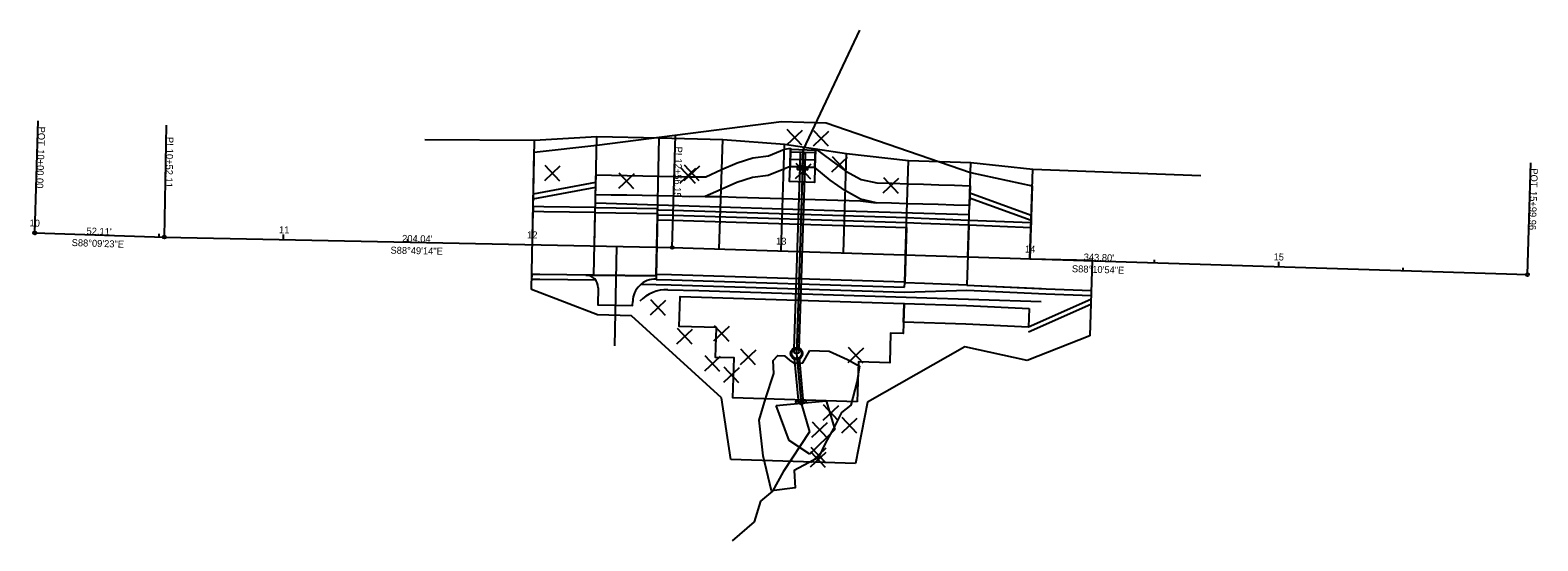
# Model space of a CAD drawing. Extents: x 2005219 to 2005824, y 572492 to 572698.
import ezdxf

# ---------------------------------------------------------------- set-up
doc = ezdxf.new("R2010")
doc.units = 0
for name, color, linetype in [('DR_P_Headwall', 7, 'Continuous'), ('GE_P_Alignment', 7, 'Continuous'), ('GE_P_Alignment_100_Bearings', 7, 'Continuous'), ('GE_P_Alignment_100_Cardinal_Points', 7, 'Continuous'), ('GE_P_Alignment_100_Distances', 7, 'Continuous'), ('GE_P_Alignment_100_Stations', 7, 'Continuous'), ('GE_X_Alignment_1000_Bearings', 7, 'Continuous'), ('GE_X_Alignment_1000_Cardinal_Points', 7, 'Continuous'), ('GE_X_Alignment_1000_Curve_Data', 7, 'Continuous'), ('GE_X_Alignment_1000_Distances', 7, 'Continuous'), ('GE_X_Alignment_1000_Stations', 7, 'Continuous'), ('GE_X_Alignment_100_Cardinal_Points', 7, 'Continuous'), ('GE_X_Alignment_100_Curve_Data', 7, 'Continuous'), ('GE_X_Alignment_100_Distances', 7, 'Continuous'), ('GE_X_Alignment_100_Stations', 7, 'Continuous'), ('GE_X_Alignment_500_Bearings', 7, 'Continuous'), ('GE_X_Alignment_500_Cardinal_Points', 7, 'Continuous'), ('GE_X_Alignment_500_Curve_Data', 7, 'Continuous'), ('GE_X_Alignment_500_Stations', 7, 'Continuous'), ('GK_Drainage_Nodes', 7, 'Continuous'), ('PV_P_Drive', 7, 'Continuous'), ('PV_P_EOP', 7, 'Continuous'), ('PV_P_Shoulder', 7, 'Continuous'), ('RD_P_GR_Rt', 7, 'Continuous'), ('RW_X_CL', 7, 'Continuous'), ('RW_X_Esmt_ES', 7, 'Continuous')]:
    doc.layers.add(name, color=color, linetype=linetype)

msp = doc.modelspace()

# ---------------------------------------------------------------- linework, layer by layer
at = {"layer": 'DR_P_Headwall'}
for points in [[(2005527.91, 572642.55), (2005527.87, 572641.55), (2005526.88, 572641.58), (2005526.91, 572642.58), (2005530.9, 572642.45), (2005530.87, 572641.45), (2005529.87, 572641.48), (2005529.91, 572642.48)], [(2005529.36, 572547.73), (2005529.27, 572548.72), (2005530.26, 572548.82), (2005530.35, 572547.82), (2005526.37, 572547.45), (2005526.28, 572548.45), (2005527.27, 572548.54), (2005527.37, 572547.55)]]:
    msp.add_lwpolyline(points, dxfattribs=at)
at = {"layer": 'GE_P_Alignment'}
for p, q in [((2005220.42, 572616.04), (2005272.51, 572614.37)), ((2005272.51, 572614.37), (2005476.5, 572610.17)), ((2005476.5, 572610.17), (2005820.14, 572599.26))]:
    msp.add_line(p, q, dxfattribs=at)
at = {"layer": 'GE_P_Alignment_100_Cardinal_Points'}
for p, q in [((2005220.42, 572616.04), (2005221.87, 572661.02)), ((2005272.51, 572614.37), (2005273.44, 572659.36)), ((2005476.5, 572610.17), (2005477.93, 572655.14)), ((2005820.14, 572599.26), (2005821.56, 572644.24))]:
    msp.add_line(p, q, dxfattribs=at)
for centre in [(2005220.42, 572616.04), (2005272.51, 572614.37), (2005476.5, 572610.17), (2005820.14, 572599.26)]:
    msp.add_circle(centre, 0.6, dxfattribs=at)
at = {"layer": 'GE_P_Alignment_100_Stations'}
for p, q in [((2005220.42, 572616.04), (2005220.49, 572618.04)), ((2005270.4, 572614.44), (2005270.44, 572615.63)), ((2005320.39, 572613.38), (2005320.43, 572615.38)), ((2005370.38, 572612.35), (2005370.4, 572613.55)), ((2005420.37, 572611.32), (2005420.41, 572613.32)), ((2005470.35, 572610.29), (2005470.38, 572611.49)), ((2005520.33, 572608.78), (2005520.39, 572610.77)), ((2005570.31, 572607.19), (2005570.34, 572608.39)), ((2005620.28, 572605.6), (2005620.34, 572607.6)), ((2005670.26, 572604.02), (2005670.29, 572605.22)), ((2005720.23, 572602.43), (2005720.29, 572604.43)), ((2005770.21, 572600.84), (2005770.24, 572602.04))]:
    msp.add_line(p, q, dxfattribs=at)
at = {"layer": 'GE_X_Alignment_1000_Bearings'}
for p, q in [((2005524.14, 572650.06), (2005523.91, 572642.67)), ((2005524.14, 572650.06), (2005523.91, 572642.67)), ((2005533.9, 572642.36), (2005534.17, 572649.85)), ((2005533.9, 572642.36), (2005534.17, 572649.85)), ((2005445.78, 572631.4), (2005445.95, 572639.4)), ((2005445.78, 572631.4), (2005445.95, 572639.4)), ((2005596.2, 572634.99), (2005595.94, 572627)), ((2005596.2, 572634.99), (2005595.94, 572627)), ((2005493.96, 572565.99), (2005494.34, 572577.99)), ((2005518.26, 572546.7), (2005538.47, 572548.57)), ((2005523.49, 572532.62), (2005518.26, 572546.7)), ((2005538.47, 572548.57), (2005541.87, 572536.98)), ((2005541.87, 572536.98), (2005531.82, 572527.09)), ((2005531.82, 572527.09), (2005523.49, 572532.62))]:
    msp.add_line(p, q, dxfattribs=at)
for points in [[(2005490, 572638.62), (2005496.35, 572641.55), (2005502.69, 572644.27), (2005509, 572646.28), (2005515.28, 572647.06), (2005521.62, 572649.64), (2005524.14, 572650.06)], [(2005490, 572638.62), (2005496.35, 572641.55), (2005502.69, 572644.27), (2005509, 572646.28), (2005515.28, 572647.06), (2005521.62, 572649.64), (2005524.14, 572650.06)], [(2005534.17, 572649.85), (2005540.25, 572645.28), (2005546.36, 572640.89), (2005552.51, 572637.55), (2005558.72, 572636.17)], [(2005534.17, 572649.85), (2005540.25, 572645.28), (2005546.36, 572640.89), (2005552.51, 572637.55), (2005558.72, 572636.17)], [(2005523.91, 572642.67), (2005521.36, 572641.64), (2005515.12, 572639.06), (2005508.84, 572638.28), (2005502.52, 572636.27), (2005496.18, 572633.55), (2005489.84, 572630.62)], [(2005523.91, 572642.67), (2005521.36, 572641.64), (2005515.12, 572639.06), (2005508.84, 572638.28), (2005502.52, 572636.27), (2005496.18, 572633.55), (2005489.84, 572630.62)], [(2005558.47, 572628.18), (2005552.26, 572629.55), (2005546.11, 572632.9), (2005540, 572637.29), (2005533.9, 572642.36)], [(2005558.47, 572628.18), (2005552.26, 572629.55), (2005546.11, 572632.9), (2005540, 572637.29), (2005533.9, 572642.36)], [(2005445.95, 572639.4), (2005452.2, 572639.27), (2005458.45, 572639.14), (2005464.69, 572639.02), (2005470.93, 572638.89), (2005477.5, 572638.75), (2005483.75, 572638.55), (2005490, 572638.62)], [(2005445.95, 572639.4), (2005452.2, 572639.27), (2005458.45, 572639.14), (2005464.69, 572639.02), (2005470.93, 572638.89), (2005477.5, 572638.75), (2005483.75, 572638.55), (2005490, 572638.62)], [(2005558.72, 572636.17), (2005564.97, 572635.97), (2005571.21, 572635.77), (2005577.46, 572635.59), (2005583.71, 572635.39), (2005589.95, 572635.19), (2005596.2, 572634.99)], [(2005558.72, 572636.17), (2005564.97, 572635.97), (2005571.21, 572635.77), (2005577.46, 572635.59), (2005583.71, 572635.39), (2005589.95, 572635.19), (2005596.2, 572634.99)], [(2005489.84, 572630.62), (2005483.58, 572630.55), (2005477.33, 572630.75), (2005470.77, 572630.89), (2005464.53, 572631.02), (2005458.28, 572631.15), (2005452.03, 572631.27), (2005445.78, 572631.4)], [(2005489.84, 572630.62), (2005483.58, 572630.55), (2005477.33, 572630.75), (2005470.77, 572630.89), (2005464.53, 572631.02), (2005458.28, 572631.15), (2005452.03, 572631.27), (2005445.78, 572631.4)], [(2005595.94, 572627), (2005589.7, 572627.19), (2005583.45, 572627.39), (2005577.21, 572627.59), (2005570.96, 572627.78), (2005564.71, 572627.98), (2005558.47, 572628.18)], [(2005595.94, 572627), (2005589.7, 572627.19), (2005583.45, 572627.39), (2005577.21, 572627.59), (2005570.96, 572627.78), (2005564.71, 572627.98), (2005558.47, 572628.18)]]:
    msp.add_lwpolyline(points, dxfattribs=at)
for points in [[(2005533.71, 572636.36), (2005523.72, 572636.68), (2005523.91, 572642.67), (2005526.91, 572642.58), (2005526.88, 572641.58), (2005530.87, 572641.45), (2005530.9, 572642.45), (2005533.9, 572642.36)], [(2005550.92, 572548.17), (2005500.95, 572549.76), (2005501.46, 572565.75), (2005493.96, 572565.99), (2005494.34, 572577.99), (2005479.35, 572578.46), (2005479.73, 572590.46), (2005569.68, 572587.6), (2005569.3, 572575.61), (2005564.31, 572575.76), (2005563.92, 572563.77), (2005551.43, 572564.17)], [(2005550.92, 572548.17), (2005500.95, 572549.76), (2005501.46, 572565.75), (2005493.96, 572565.99), (2005494.34, 572577.99), (2005479.35, 572578.46), (2005479.73, 572590.46), (2005569.68, 572587.6), (2005569.3, 572575.61), (2005564.31, 572575.76), (2005563.92, 572563.77), (2005551.43, 572564.17)]]:
    msp.add_lwpolyline(points, close=True, dxfattribs=at)
at = {"layer": 'GE_X_Alignment_1000_Cardinal_Points'}
for centre, radius in [((2005526.53, 572567.55), 2.42), ((2005526.53, 572567.55), 2), ((2005526.55, 572568.41), 0.99)]:
    msp.add_circle(centre, radius, dxfattribs=at)
at = {"layer": 'GE_X_Alignment_1000_Curve_Data'}
for p, q in [((2005420.37, 572611.32), (2005421.23, 572653.31)), ((2005445.36, 572610.81), (2005446.27, 572654.8)), ((2005470.35, 572610.29), (2005471.26, 572654.28)), ((2005495.44, 572609.57), (2005496.84, 572653.54)), ((2005520.33, 572608.78), (2005521.7, 572651.75)), ((2005523.89, 572642.17), (2005524.11, 572649.17)), ((2005545.32, 572607.98), (2005546.59, 572647.96)), ((2005570.31, 572607.19), (2005571.51, 572645.17)), ((2005595.29, 572606.4), (2005596.5, 572644.38)), ((2005620.28, 572605.7), (2005621.43, 572641.68))]:
    msp.add_line(p, q, dxfattribs=at)
msp.add_circle((2005526.53, 572567.55), 2, dxfattribs=at)
at = {"layer": 'GE_X_Alignment_1000_Distances'}
msp.add_line((2005454.14, 572610.63), (2005453.32, 572570.64), dxfattribs=at)
at = {"layer": 'GE_X_Alignment_1000_Stations'}
for p, q in [((2005522.56, 572651.45), (2005528.84, 572657.35)), ((2005528.65, 572651.26), (2005522.75, 572657.54)), ((2005533.25, 572651.04), (2005539.53, 572656.94)), ((2005539.34, 572650.85), (2005533.44, 572657.13)), ((2005540.7, 572640.57), (2005546.98, 572646.46)), ((2005546.79, 572640.37), (2005540.89, 572646.66)), ((2005425.32, 572637.05), (2005431.6, 572642.94)), ((2005431.41, 572636.85), (2005425.51, 572643.14)), ((2005455.08, 572634), (2005461.36, 572639.9)), ((2005461.17, 572633.81), (2005455.27, 572640.09)), ((2005479.78, 572636.13), (2005486.06, 572642.03)), ((2005485.87, 572635.94), (2005479.97, 572642.22)), ((2005481.33, 572637.14), (2005487.61, 572643.04)), ((2005487.42, 572636.95), (2005481.52, 572643.23)), ((2005526.12, 572637.87), (2005532.4, 572643.77)), ((2005532.21, 572637.68), (2005526.32, 572643.96)), ((2005561.33, 572632.11), (2005567.62, 572638.01)), ((2005567.42, 572631.92), (2005561.53, 572638.2)), ((2005467.77, 572583.04), (2005474.05, 572588.93)), ((2005473.86, 572582.84), (2005467.96, 572589.13)), ((2005478.46, 572571.46), (2005484.74, 572577.36)), ((2005484.54, 572571.27), (2005478.65, 572577.55)), ((2005493.34, 572572.59), (2005499.63, 572578.49)), ((2005499.43, 572572.4), (2005493.54, 572578.68)), ((2005503.93, 572563.15), (2005510.22, 572569.04)), ((2005510.02, 572562.95), (2005504.13, 572569.24)), ((2005547.23, 572563.91), (2005553.52, 572569.81)), ((2005553.32, 572563.72), (2005547.43, 572570)), ((2005489.61, 572560.56), (2005495.9, 572566.46)), ((2005495.7, 572560.37), (2005489.81, 572566.65)), ((2005497.25, 572556.03), (2005503.54, 572561.92)), ((2005503.34, 572555.83), (2005497.45, 572562.12)), ((2005537.17, 572540.82), (2005543.46, 572546.71)), ((2005543.26, 572540.62), (2005537.37, 572546.91)), ((2005532.67, 572533.86), (2005538.95, 572539.76)), ((2005538.76, 572533.67), (2005532.86, 572539.95)), ((2005544.64, 572535.68), (2005550.92, 572541.57)), ((2005550.73, 572535.48), (2005544.83, 572541.77)), ((2005532.09, 572521.98), (2005538.37, 572527.88)), ((2005532.18, 572523.74), (2005538.47, 572529.64)), ((2005538.18, 572521.79), (2005532.28, 572528.07)), ((2005538.27, 572523.55), (2005532.38, 572529.83))]:
    msp.add_line(p, q, dxfattribs=at)
at = {"layer": 'GE_X_Alignment_100_Cardinal_Points'}
for p, q in [((2005446.24, 572651.27), (2005520.48, 572660.79)), ((2005520.48, 572660.79), (2005538.47, 572660.22)), ((2005538.47, 572660.22), (2005596.37, 572640.34)), ((2005420, 572593.35), (2005421.13, 572648.48)), ((2005421.13, 572648.48), (2005446.24, 572651.27)), ((2005596.37, 572640.34), (2005621.21, 572634.96)), ((2005621.21, 572634.96), (2005620.28, 572605.6)), ((2005620.28, 572605.6), (2005645.28, 572605.03)), ((2005645.28, 572605.03), (2005644.31, 572574.61)), ((2005446.53, 572583.14), (2005420, 572593.35)), ((2005460.56, 572589.71), (2005460.56, 572589.71)), ((2005460.17, 572582.71), (2005446.53, 572583.14)), ((2005496.33, 572549.72), (2005460.17, 572582.71)), ((2005644.31, 572574.61), (2005619.16, 572564.73)), ((2005594.14, 572570.19), (2005555, 572547.97)), ((2005619.16, 572564.73), (2005594.14, 572570.19)), ((2005500.16, 572524.96), (2005496.33, 572549.72)), ((2005555, 572547.97), (2005550.14, 572523.37)), ((2005550.14, 572523.37), (2005500.16, 572524.96))]:
    msp.add_line(p, q, dxfattribs=at)
at = {"layer": 'GE_X_Alignment_100_Curve_Data'}
for p, q in [((2005445.91, 572628.15), (2005495.88, 572626.56)), ((2005495.88, 572626.56), (2005545.86, 572624.97)), ((2005545.86, 572624.97), (2005595.83, 572623.39))]:
    msp.add_line(p, q, dxfattribs=at)
at = {"layer": 'GE_X_Alignment_100_Distances'}
for points in [[(2005489.84, 572630.62), (2005496.01, 572630.66), (2005502.26, 572630.46), (2005552.23, 572628.87), (2005558.47, 572628.18), (2005552.26, 572629.55), (2005546.11, 572632.9), (2005540, 572637.29), (2005533.9, 572642.36), (2005533.71, 572636.36), (2005523.72, 572636.68), (2005523.91, 572642.67), (2005521.36, 572641.64), (2005515.12, 572639.06), (2005515.12, 572639.06), (2005508.84, 572638.28), (2005502.52, 572636.27), (2005496.18, 572633.55)], [(2005489.84, 572630.62), (2005496.01, 572630.66), (2005502.26, 572630.46), (2005552.23, 572628.87), (2005558.47, 572628.18), (2005552.26, 572629.55), (2005546.11, 572632.9), (2005540, 572637.29), (2005533.9, 572642.36), (2005533.71, 572636.36), (2005523.72, 572636.68), (2005523.91, 572642.67), (2005521.36, 572641.64), (2005515.12, 572639.06), (2005515.12, 572639.06), (2005508.84, 572638.28), (2005502.52, 572636.27), (2005496.18, 572633.55)], [(2005619.94, 572585.67), (2005619.71, 572578.2), (2005594.53, 572579.32), (2005569.45, 572580.12), (2005569.68, 572587.6), (2005594.77, 572586.8)], [(2005619.94, 572585.67), (2005619.71, 572578.2), (2005594.53, 572579.32), (2005569.45, 572580.12), (2005569.68, 572587.6), (2005594.77, 572586.8)]]:
    msp.add_lwpolyline(points, close=True, dxfattribs=at)
at = {"layer": 'GE_X_Alignment_100_Stations'}
for points in [[(2005529.42, 572643), (2005529.39, 572642), (2005528.39, 572642.03), (2005528.42, 572643.03)], [(2005527.91, 572547.09), (2005527.82, 572548.09), (2005528.81, 572548.18), (2005528.91, 572547.19)]]:
    msp.add_lwpolyline(points, close=True, dxfattribs=at)
at = {"layer": 'GE_X_Alignment_500_Bearings'}
for p, q in [((2005528.91, 572642.51), (2005526.59, 572569.55)), ((2005526.71, 572565.56), (2005528.36, 572547.64))]:
    msp.add_line(p, q, dxfattribs=at)
at = {"layer": 'GE_X_Alignment_500_Cardinal_Points'}
for p, q in [((2005525.58, 572569.32), (2005527.91, 572642.55)), ((2005527.58, 572569.25), (2005529.91, 572642.48)), ((2005527.37, 572547.55), (2005525.69, 572565.74)), ((2005529.36, 572547.73), (2005527.68, 572565.92))]:
    msp.add_line(p, q, dxfattribs=at)
at = {"layer": 'GE_X_Alignment_500_Curve_Data'}
for p, q in [((2005524, 572645.67), (2005534, 572645.35)), ((2005524.1, 572648.67), (2005534.09, 572648.35)), ((2005527.91, 572642.55), (2005528.1, 572648.54)), ((2005528.91, 572642.51), (2005529.13, 572649.51)), ((2005529.91, 572642.48), (2005530.1, 572648.48))]:
    msp.add_line(p, q, dxfattribs=at)
msp.add_lwpolyline([(2005524.13, 572649.67), (2005534.13, 572649.35), (2005533.9, 572642.36), (2005523.91, 572642.67)], close=True, dxfattribs=at)
msp.add_lwpolyline([(2005524.13, 572649.67), (2005534.13, 572649.35), (2005533.9, 572642.36), (2005523.91, 572642.67)], close=True, dxfattribs=at)
at = {"layer": 'GE_X_Alignment_500_Stations'}
for p, q in [((2005551.77, 572697.55), (2005529.13, 572649.51)), ((2005529.13, 572649.51), (2005526.53, 572567.55)), ((2005420.73, 572629.68), (2005445.83, 572634.4)), ((2005420.8, 572631.68), (2005445.9, 572636.4)), ((2005620.77, 572621.04), (2005596.04, 572629.99)), ((2005620.83, 572623.04), (2005596.1, 572631.99)), ((2005644.71, 572587.23), (2005619.64, 572576.2)), ((2005644.77, 572589.22), (2005619.71, 572578.2)), ((2005526.53, 572567.55), (2005528.36, 572547.64)), ((2005528.36, 572547.64), (2005531.76, 572536.05)), ((2005531.76, 572536.05), (2005521.07, 572519.95)), ((2005521.07, 572519.95), (2005516.88, 572512.2)), ((2005511.96, 572508.18), (2005509.48, 572499.91)), ((2005516.88, 572512.2), (2005511.96, 572508.18)), ((2005509.48, 572499.91), (2005500.59, 572492.24))]:
    msp.add_line(p, q, dxfattribs=at)
at = {"layer": 'GK_Drainage_Nodes'}
for p, q in [((2005528.87, 572641.52), (2005528.87, 572641.52)), ((2005528.91, 572642.51), (2005528.91, 572642.51)), ((2005528.91, 572642.51), (2005528.91, 572642.51)), ((2005528.91, 572642.51), (2005528.91, 572642.51)), ((2005528.91, 572642.51), (2005528.91, 572642.51)), ((2005528.91, 572642.51), (2005528.91, 572642.51)), ((2005528.27, 572548.63), (2005528.27, 572548.63)), ((2005528.36, 572547.64), (2005528.36, 572547.64)), ((2005528.36, 572547.64), (2005528.36, 572547.64)), ((2005528.36, 572547.64), (2005528.36, 572547.64)), ((2005528.36, 572547.64), (2005528.36, 572547.64)), ((2005528.36, 572547.64), (2005528.36, 572547.64))]:
    msp.add_line(p, q, dxfattribs=at)
at = {"layer": 'PV_P_Drive'}
for points in [[(2005441.9, 572599.07), (2005445.12, 572599.02), (2005470.12, 572598.73), (2005470.07, 572597.49)], [(2005446.8, 572593.96), (2005446.66, 572587.14), (2005460.65, 572586.85), (2005460.69, 572588.48)]]:
    msp.add_lwpolyline(points, dxfattribs=at)
for centre, radius, start, end in [((2005441.8, 572594.07), 5, 358.82055, 88.82055), ((2005469.88, 572588.29), 9.2, 88.82055, 178.82055)]:
    msp.add_arc(centre, radius, start, end, dxfattribs=at)
at = {"layer": 'PV_P_EOP'}
msp.add_line((2005470.38, 572611.49), (2005470.38, 572611.49), dxfattribs=at)
for points in [[(2005445.12, 572599.02), (2005445.64, 572624.22), (2005470.63, 572623.81), (2005470.12, 572598.73)], [(2005476.28, 572599.17), (2005470.13, 572599.3), (2005470.58, 572621.29), (2005476.73, 572621.16), (2005570.65, 572618.18), (2005569.96, 572596.19)], [(2005595.7, 572619.22), (2005594.93, 572595), (2005577.92, 572595.76), (2005569.95, 572596), (2005570.72, 572620.19), (2005576.56, 572620.01)]]:
    msp.add_lwpolyline(points, close=True, dxfattribs=at)
at = {"layer": 'PV_P_Shoulder'}
for p, q in [((2005420.68, 572626.6), (2005420.64, 572624.6)), ((2005445.68, 572626.22), (2005470.67, 572625.81)), ((2005470.67, 572625.81), (2005470.66, 572625.29)), ((2005470.66, 572625.29), (2005471.18, 572625.28)), ((2005570.78, 572622.19), (2005570.78, 572622.18)), ((2005595.7, 572619.22), (2005620.68, 572618.2)), ((2005595.76, 572621.22), (2005620.74, 572620.2)), ((2005620.74, 572620.2), (2005620.68, 572618.2)), ((2005420.12, 572599.35), (2005420.08, 572597.35)), ((2005470.12, 572598.73), (2005470.09, 572597.3)), ((2005569.89, 572594.2), (2005569.95, 572596)), ((2005594.87, 572593), (2005626.66, 572591.58)), ((2005594.93, 572595), (2005626.73, 572593.57)), ((2005594.93, 572595), (2005624.96, 572593.65)), ((2005626.66, 572591.58), (2005644.83, 572590.85)), ((2005626.73, 572593.57), (2005644.89, 572592.85)), ((2005644.89, 572592.85), (2005644.83, 572590.85))]:
    msp.add_line(p, q, dxfattribs=at)
for points in [[(2005445.64, 572624.22), (2005425, 572624.56), (2005420.64, 572624.6)], [(2005445.68, 572626.22), (2005425.04, 572626.56), (2005420.68, 572626.6)], [(2005470.62, 572623.29), (2005476.79, 572623.16), (2005570.72, 572620.18)], [(2005470.66, 572625.29), (2005476.86, 572625.16), (2005570.78, 572622.18)], [(2005570.78, 572622.19), (2005576.63, 572622.01), (2005595.76, 572621.22)], [(2005445.84, 572597.01), (2005423.37, 572597.27), (2005420.08, 572597.35)], [(2005445.12, 572599.02), (2005423.43, 572599.27), (2005420.12, 572599.35)], [(2005470.09, 572597.3), (2005476.21, 572597.17), (2005569.89, 572594.2)], [(2005464.1, 572595.42), (2005476.15, 572595.17), (2005569.83, 572592.2)], [(2005569.83, 572592.2), (2005569.83, 572592.2), (2005594.87, 572593)]]:
    msp.add_lwpolyline(points, dxfattribs=at)
at = {"layer": 'RD_P_GR_Rt'}
for p, q in [((2005474.81, 572593.21), (2005487.31, 572592.82)), ((2005487.31, 572592.82), (2005574.76, 572590.04)), ((2005574.76, 572590.04), (2005624.74, 572588.45))]:
    msp.add_line(p, q, dxfattribs=at)
msp.add_arc((2005474.33, 572578.22), 15, 88.15809, 135.90458, dxfattribs=at)
at = {"layer": 'RW_X_CL'}
msp.add_line((2005377.16, 572653.63), (2005421.16, 572653.31), dxfattribs=at)
msp.add_lwpolyline([(2005377.16, 572653.63), (2005421.23, 572653.31), (2005446.27, 572654.8), (2005471.26, 572654.28), (2005496.84, 572653.54), (2005521.7, 572651.75), (2005546.59, 572647.96), (2005571.51, 572645.17), (2005596.5, 572644.38), (2005621.43, 572641.68), (2005688.9, 572639.14)], dxfattribs=at)
at = {"layer": 'RW_X_Esmt_ES'}
msp.add_lwpolyline([(2005531.82, 572568.71), (2005539.63, 572568.54), (2005546.98, 572565.21), (2005551.78, 572562.46), (2005550.74, 572556.04), (2005548.29, 572546.83), (2005544.6, 572543.9), (2005541.31, 572537.45), (2005538.15, 572531.63), (2005535.27, 572525.77), (2005525.49, 572520.52), (2005525.94, 572513.57), (2005516.42, 572512.4), (2005513.04, 572526.41), (2005511.45, 572540.78), (2005514.09, 572549.34), (2005517.33, 572559.48), (2005517.08, 572564.8), (2005519.03, 572566.72), (2005521.65, 572566.59), (2005523.72, 572564.87), (2005525.44, 572563.63), (2005529.05, 572563.82), (2005531.82, 572568.71)], dxfattribs=at)

# ---------------------------------------------------------------- texts
at = {"layer": 'GE_P_Alignment_100_Bearings'}
for s, rotation, p in [('S88°09\'23"E', 358.15631, (2005235.24, 572610.76)), ('S88°49\'14"E', 358.82055, (2005363.34, 572607.7)), ('S88°10\'54"E', 358.18163, (2005637.1, 572600.27))]:
    msp.add_text(s, height=2.8, rotation=rotation, dxfattribs=at).set_placement(p)
at = {"layer": 'GE_P_Alignment_100_Cardinal_Points'}
for s, rotation, p in [('POT', 268.15631, (2005221.85, 572658.81)), ('PI', 268.82055, (2005273.39, 572654.66)), ('10+00.00', 268.15631, (2005221.55, 572649.69)), ('10+52.11', 268.82055, (2005273.29, 572649.88)), ('12+56.15', 268.18163, (2005477.69, 572646)), ('PI', 268.18163, (2005477.84, 572650.78)), ('POT', 268.18163, (2005821.54, 572642.03)), ('15+99.96', 268.18163, (2005821.25, 572632.91))]:
    msp.add_text(s, height=2.8, rotation=rotation, dxfattribs=at).set_placement(p)
at = {"layer": 'GE_P_Alignment_100_Distances'}
for s, rotation, p in [("52.11'", 358.15631, (2005241.22, 572615.42)), ("204.04'", 358.82055, (2005368.02, 572612.45)), ("343.80'", 358.18163, (2005641.84, 572604.97))]:
    msp.add_text(s, height=2.8, rotation=rotation, dxfattribs=at).set_placement(p)
at = {"layer": 'GE_P_Alignment_100_Stations'}
for s, rotation, p in [('10', 358.15631, (2005218.31, 572618.66)), ('11', 358.82055, (2005318.56, 572615.92)), ('12', 358.82055, (2005418.23, 572613.87)), ('13', 358.18163, (2005518.24, 572611.39)), ('14', 358.18163, (2005618.21, 572608.17)), ('15', 358.18163, (2005718.11, 572605.05))]:
    msp.add_text(s, height=2.8, rotation=rotation, dxfattribs=at).set_placement(p)

doc.saveas('drawing.dxf')
